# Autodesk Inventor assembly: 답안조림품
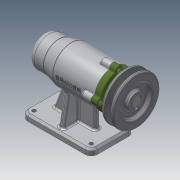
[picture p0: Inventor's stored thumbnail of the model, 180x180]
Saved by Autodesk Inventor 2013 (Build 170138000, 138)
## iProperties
Created: 2019-07
Part Number: 답안조림품
Document SubType Name: Assembly
Designer: user
Author: user
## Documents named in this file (12)
- C:\Users\user\Desktop\490704V1046\답안조림품.iam
- C:\Users\user\Desktop\490704V1046\본체.ipt
- C:\Users\user\Desktop\490704V1046\V벨트풀리.ipt
- C:\Users\user\Desktop\490704V1046\멈춤나사 M3.ipt
- C:\Users\user\Desktop\490704V1046\베어링 6004.ipt
- C:\Users\user\Desktop\490704V1046\베어링 51202.ipt
- C:\Users\user\Desktop\490704V1046\볼트 M4.ipt
- C:\Users\user\Desktop\490704V1046\어댑터슬리브.ipt
- C:\Users\user\Desktop\490704V1046\오일 실.ipt
- C:\Users\user\Desktop\490704V1046\축.ipt
- C:\Users\user\Desktop\490704V1046\커버.ipt
- C:\Users\user\Desktop\490704V1046\키 5 x 5 x 16.ipt
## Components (1 placed, 1 different names)
1. V벨트풀리:1
